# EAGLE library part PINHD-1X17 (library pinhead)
PIN HEADER
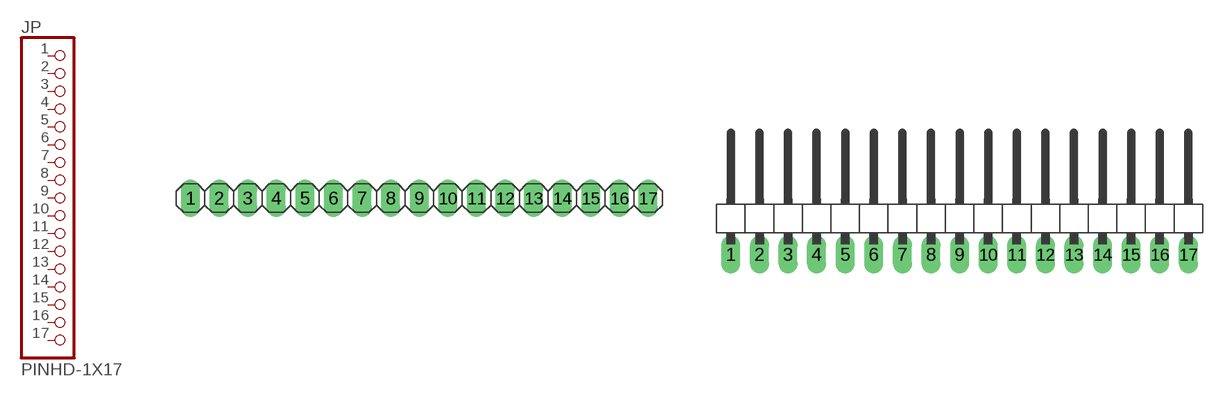
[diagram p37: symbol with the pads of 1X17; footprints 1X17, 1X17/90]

Designator prefix JP

## PINHD-1X17  [1X17]
1  1  pas
2  2  pas
3  3  pas
4  4  pas
5  5  pas
6  6  pas
7  7  pas
8  8  pas
9  9  pas
10  10  pas
11  11  pas
12  12  pas
13  13  pas
14  14  pas
15  15  pas
16  16  pas
17  17  pas

## PINHD-1X17/90  [1X17/90]
Pads as for 1X17

## Footprint 1X17 (pad centres in mm)
PIN HEADER
drill 1.016 pad 1.67 long: 1 -20.32,0; 2 -17.78,0; 3 -15.24,0; 4 -12.7,0; 5 -10.16,0; 6 -7.62,0; 7 -5.08,0; 8 -2.54,0; 9 0,0; 10 2.54,0; 11 5.08,0; 12 7.62,0; 13 10.16,0; 14 12.7,0; 15 15.24,0; 16 17.78,0; 17 20.32,0

## Footprint 1X17/90 (pad centres in mm)
PIN HEADER
drill 1.016 pad 1.67 long: 1 -20.32,-3.81; 2 -17.78,-3.81; 3 -15.24,-3.81; 4 -12.7,-3.81; 5 -10.16,-3.81; 6 -7.62,-3.81; 7 -5.08,-3.81; 8 -2.54,-3.81; 9 0,-3.81; 10 2.54,-3.81; 11 5.08,-3.81; 12 7.62,-3.81; 13 10.16,-3.81; 14 12.7,-3.81; 15 15.24,-3.81; 16 17.78,-3.81; 17 20.32,-3.81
